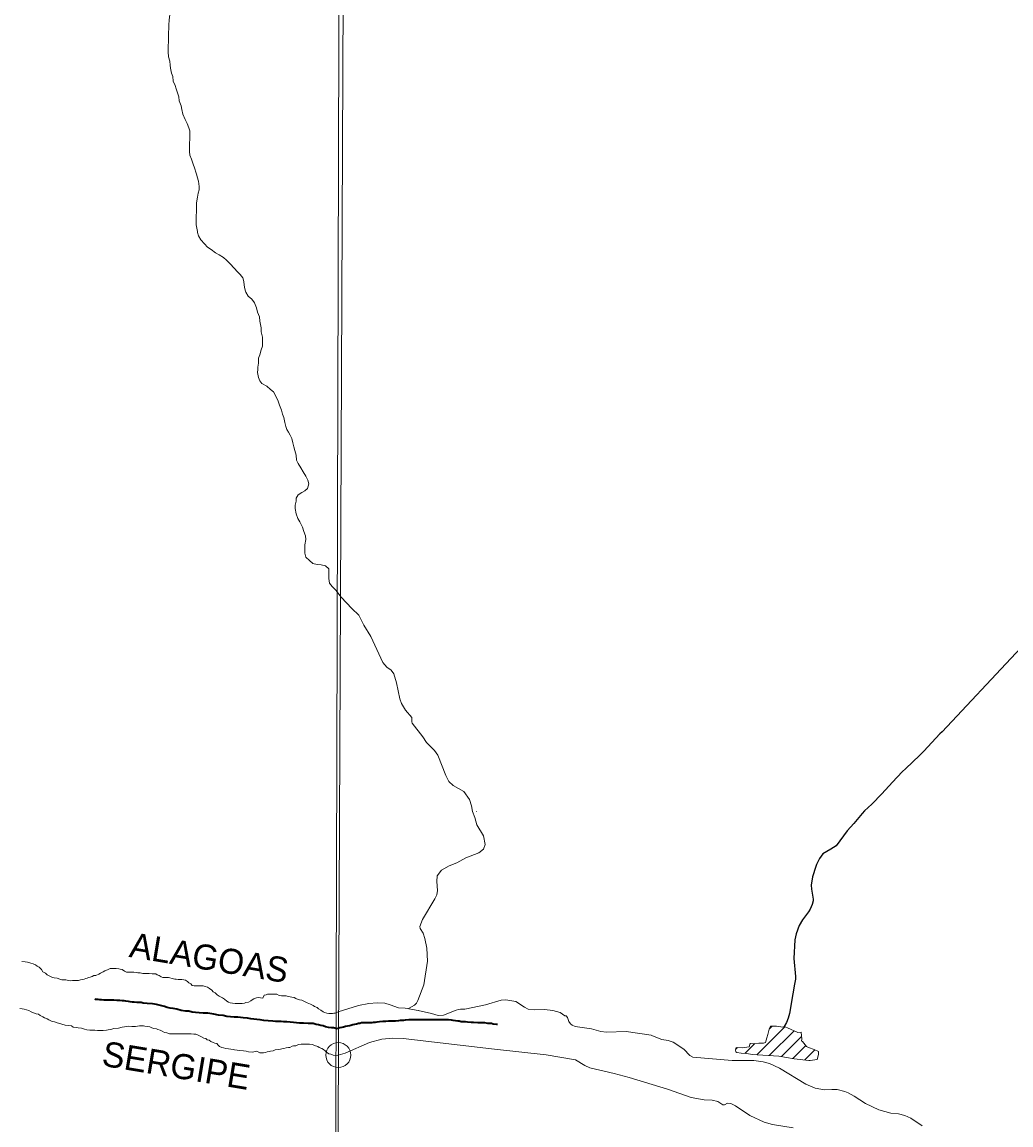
# Model space of a CAD drawing. Extents: x -1643653 to 4543381, y 1624270 to 13878484.
# Drawn here: x 595557 to 598718, y 8904168 to 8907693 of the extents above; entities that cross this region are included whole.
import ezdxf
from ezdxf.enums import TextEntityAlignment as Align

# ---------------------------------------------------------------- set-up
doc = ezdxf.new("R2010")
doc.units = 0
doc.header["$LTSCALE"] = 160
doc.header["$PDMODE"] = 32
doc.header["$PDSIZE"] = 80
doc.linetypes.add('LONG_DASH_SHORT_DASH', pattern=[9.9, 6, -1.2, 1.5, -1.2])
doc.layers.add('6', color=7, linetype='Continuous', lineweight=13)
doc.layers.add('60', color=7, linetype='Continuous', lineweight=13)

msp = doc.modelspace()

# ---------------------------------------------------------------- linework, layer by layer
at = {"layer": '6'}
for p, q in [((597009.3, 8905170.6), (597009.5, 8905170.5)), ((597905.6, 8904392.3), (597995.3, 8904482)), ((597945.7, 8904390), (598025, 8904469.3)), ((597946.4, 8904475.5), (597954.7, 8904483.9)), ((597984.9, 8904386.8), (598049.1, 8904451)), ((597838.3, 8904409.9), (597844.2, 8904415.7)), ((597867.6, 8904396.8), (597899.4, 8904428.5)), ((598021.1, 8904380.5), (598062.5, 8904421.9)), ((598059, 8904376), (598091.6, 8904408.6))]:
    msp.add_line(p, q, dxfattribs=at)
for points in [[(596655.5, 8924715.8), (596593.3, 8909930.3), (596531.7, 8896026.7)], [(596049.9, 8907479.9), (596046.2, 8907490.3), (596040.2, 8907503.9), (596038.8, 8907519.4), (596035.3, 8907529.4), (596031.9, 8907545.5), (596030.4, 8907555.5), (596029.5, 8907568.5), (596025.6, 8907582), (596024.6, 8907598.1), (596024.9, 8907649.1), (596025.4, 8907658.6), (596026, 8907674.1), (596026.5, 8907683.6), (596027.6, 8907700.1), (596029.2, 8907716.6), (596029.4, 8907756.2), (596027.9, 8907771.7), (596025, 8907786.7), (596022.6, 8907799.7), (596019.1, 8907808.8), (596014.2, 8907819.3), (596014.3, 8907828.6)], [(596115.7, 8907204.3), (596113.9, 8907210.7), (596108, 8907227.8), (596104.5, 8907239.3), (596099.1, 8907254.8), (596093.7, 8907267.4), (596092.7, 8907279.4), (596093, 8907346), (596090.6, 8907355.5), (596085.1, 8907369.5), (596078.2, 8907382.1), (596070.8, 8907398.6), (596067.8, 8907413.7), (596065.4, 8907425.2), (596059.4, 8907441.7), (596058, 8907454.7), (596055, 8907464.3), (596049.9, 8907479.9)], [(596117.5, 8907024.2), (596116.1, 8907034), (596114.2, 8907044.6), (596114.5, 8907115.1), (596118.1, 8907133.1), (596120.6, 8907146.6), (596123.2, 8907157.1), (596123.2, 8907168.1), (596121.3, 8907184.2), (596117.4, 8907198.2), (596115.7, 8907204.3)], [(596271.3, 8906832.7), (596268.8, 8906840.6), (596267.4, 8906852.6), (596266, 8906863.6), (596262.5, 8906875.6), (596254.5, 8906886.2), (596246.1, 8906895.2), (596235.1, 8906906.3), (596222.2, 8906920.4), (596211.2, 8906932.4), (596201.2, 8906941), (596187.3, 8906949.1), (596175.3, 8906955.7), (596161.8, 8906966.2), (596149.8, 8906973.8), (596139.9, 8906984.4), (596128.4, 8906996.9), (596121.5, 8907010), (596118, 8907020.5), (596117.5, 8907024.2)], [(596279.7, 8906817), (596272.3, 8906829.5), (596271.3, 8906832.7)], [(596461.2, 8906005.4), (596461.2, 8906022.7), (596463.8, 8906039.2), (596463.4, 8906051.2), (596457.4, 8906065.3), (596453.5, 8906078.3), (596444.6, 8906095.4), (596439.1, 8906106.9), (596433.7, 8906120.9), (596429.8, 8906138.5), (596429.8, 8906149), (596432.9, 8906162), (596433.9, 8906171.5), (596439.5, 8906182), (596451, 8906189.9), (596461, 8906195.4), (596470.1, 8906202.3), (596474.2, 8906216.8), (596471.2, 8906229.4), (596464.2, 8906241.4), (596455.8, 8906256), (596447.9, 8906268), (596439.9, 8906282.6), (596434.5, 8906292.6), (596433, 8906308.7), (596429.1, 8906323.7), (596426.2, 8906335.2), (596422.7, 8906348.8), (596419.3, 8906361.8), (596413.8, 8906373.3), (596408.8, 8906382.4), (596403.4, 8906390.9), (596399.9, 8906400.4), (596397, 8906413.4), (596393.6, 8906429), (596389.6, 8906440), (596386.2, 8906452.6), (596379.7, 8906468.6), (596376.3, 8906481.6), (596368.8, 8906497.2), (596361.4, 8906511.2), (596351.4, 8906519.3), (596340, 8906529.4), (596324, 8906537.5), (596317.3, 8906546.3), (596312.9, 8906557.6), (596309.7, 8906572.8), (596311, 8906582.9), (596310.7, 8906590.6), (596312.8, 8906603.1), (596313.4, 8906618.6), (596316.9, 8906629.1), (596321.5, 8906645.1), (596325.6, 8906657.6), (596326.1, 8906673.6), (596325.7, 8906686.1), (596321.8, 8906703.6), (596321.3, 8906715.7), (596317.4, 8906737.2), (596316.5, 8906750.7), (596310, 8906765.8), (596307.1, 8906779.8), (596300.2, 8906796.3), (596291.2, 8906807.9), (596279.7, 8906817)], [(596838.8, 8905408.9), (596804, 8905452.2), (596802.6, 8905456.8), (596803.3, 8905469.9), (596782.8, 8905493.9), (596770.6, 8905515.5), (596764.7, 8905530.2), (596754.3, 8905581.4), (596745.9, 8905609.6), (596737.4, 8905621.2), (596722.8, 8905631.7), (596710.6, 8905646), (596672.1, 8905729.1), (596650.2, 8905765.8), (596633.6, 8905797.4), (596611.2, 8905818.6), (596577.4, 8905855.5), (596559.7, 8905877.5), (596548.7, 8905888.6), (596540.2, 8905900.2), (596538.3, 8905914.2), (596537.9, 8905930.7), (596537.5, 8905945.2), (596527, 8905955.3), (596513.5, 8905957.9), (596500.5, 8905959.4), (596487, 8905962.5), (596476, 8905972.6), (596464.6, 8905983.1), (596461.1, 8905995.7), (596461.2, 8906005.4)], [(596792.7, 8904540.1), (596811.4, 8904551.1), (596818.4, 8904557.4), (596822.7, 8904565.5), (596841.5, 8904615.9), (596853.2, 8904691.8), (596850.7, 8904732.7), (596845.1, 8904764.5), (596839.3, 8904781), (596829.4, 8904796.5), (596828.9, 8904802.2), (596837.1, 8904824.7), (596877.1, 8904890.7), (596882.8, 8904903.4), (596885.5, 8904918), (596882.5, 8904946.3), (596884.2, 8904964.5), (596897.9, 8904982), (596922.6, 8904996.6), (596946.5, 8905006.2), (596975.3, 8905021.5), (597017.5, 8905037.8), (597031.8, 8905049.4), (597037, 8905065), (597032.3, 8905091.9), (597011.4, 8905127.4), (597004.9, 8905150.7), (596996.7, 8905170.4), (596994.1, 8905188.6), (596987.3, 8905208), (596969.8, 8905234), (596935.4, 8905253.2), (596921.5, 8905266.1), (596912.2, 8905285.1), (596886, 8905350.5), (596875.4, 8905364.7), (596850.4, 8905390), (596838.8, 8905408.9)], [(595556.5, 8904690.4), (595567.5, 8904689.9), (595575, 8904688.3), (595585.5, 8904685.2), (595593, 8904682.7), (595599.9, 8904679.7), (595605.9, 8904675.6), (595612.4, 8904672.1), (595619.8, 8904665.5), (595623.3, 8904658), (595631.8, 8904653.4), (595637.2, 8904647.4), (595645.7, 8904643.3), (595654.7, 8904639.7), (595659.7, 8904638.2), (595669.6, 8904637.1), (595677.6, 8904633.6), (595684.1, 8904631.5)], [(595684.1, 8904631.5), (595696.6, 8904631.9), (595710.6, 8904628.3), (595718.1, 8904629.3), (595722.1, 8904629.3), (595726.6, 8904629.7), (595733.1, 8904629.7), (595737.1, 8904630.2), (595744.1, 8904632.1), (595751.7, 8904633.1), (595756.2, 8904634.6), (595760.7, 8904636), (595765.2, 8904637), (595769.2, 8904639), (595774.7, 8904640.4), (595781.2, 8904642.4), (595786.8, 8904645.4), (595793.3, 8904646.3), (595802.8, 8904650.3), (595807.8, 8904653.7), (595816.9, 8904657.2), (595821.4, 8904660.7), (595830.4, 8904663.6), (595839, 8904668.1), (595845, 8904668), (595850, 8904668), (595858, 8904667.9), (595866, 8904667.4), (595870.5, 8904665.8), (595877.5, 8904664.8), (595884.9, 8904659.7), (595891.4, 8904656.2), (595899.4, 8904656.1), (595903.4, 8904656.1), (595910.9, 8904656.1), (595914.9, 8904656), (595922.9, 8904655), (595927.4, 8904654.4), (595934.9, 8904653.9), (595943.4, 8904652.3), (595951.4, 8904652.3), (595956.4, 8904652.3), (595963.4, 8904652.2), (595973.4, 8904651.6), (595980.4, 8904651.1), (595984.9, 8904650.6), (595989.4, 8904647.5), (595995.3, 8904646), (596002.3, 8904641.9), (596006.8, 8904639.9), (596012.8, 8904639.9), (596025.8, 8904639.8), (596041.3, 8904635.2), (596045.8, 8904634.6), (596050.3, 8904633.6), (596056.3, 8904633.1), (596063.8, 8904633), (596067.8, 8904633), (596074.3, 8904632.4), (596079.3, 8904630.4), (596086.2, 8904626.9), (596090.2, 8904622.3), (596097.2, 8904619.3), (596100.7, 8904614.2), (596107.2, 8904613.2), (596113.7, 8904613.2), (596120.7, 8904613.1), (596124.7, 8904613.1), (596128.7, 8904613.1), (596136.2, 8904613), (596142.2, 8904611), (596149.6, 8904608.4), (596156.1, 8904604.4), (596163.6, 8904599.3), (596168, 8904593.3), (596174.5, 8904590.2), (596180.5, 8904583.7), (596186.9, 8904580.1), (596193.4, 8904576.1), (596197.9, 8904574.1), (596204.4, 8904570), (596211.3, 8904563.4), (596217.3, 8904560.4), (596222.8, 8904558.9), (596229.8, 8904557.3), (596238.8, 8904556.3), (596245.3, 8904556.2), (596249.3, 8904556.2), (596255.8, 8904556.1), (596260.3, 8904556.6), (596268.3, 8904557.6), (596272.8, 8904559), (596280.8, 8904561), (596288.9, 8904564.4), (596292.9, 8904567.9), (596298.4, 8904570.9), (596307, 8904574.3), (596312, 8904575.3), (596327, 8904573.2), (596331.5, 8904582.7), (596337.5, 8904584.1)], [(596337.5, 8904584.1), (596341.6, 8904585.6), (596350.1, 8904586.6), (596357.6, 8904586.5), (596364.6, 8904586), (596371.1, 8904585.9), (596379.5, 8904581.9), (596386.5, 8904581.3), (596393.5, 8904581.3), (596401.5, 8904580.7), (596408, 8904579.2), (596414, 8904578.1), (596419, 8904576.6), (596427, 8904575.5), (596432, 8904572.5), (596440, 8904569.4), (596444.5, 8904567.9), (596452, 8904566.9), (596457.4, 8904563.3), (596468.4, 8904558.2), (596478.9, 8904554.7), (596487.3, 8904550.1), (596492.3, 8904546.6), (596500.3, 8904543), (596504.3, 8904539), (596511.7, 8904535.4), (596519.2, 8904529.4), (596523.7, 8904527.8), (596531.7, 8904525.8), (596538.2, 8904524.7), (596545.2, 8904524.7), (596549.2, 8904524.7), (596554.2, 8904525.1), (596558.2, 8904525.1), (596568.1, 8904529.4), (596633, 8904549.7), (596665.5, 8904556.5), (596692.3, 8904558.4), (596717.2, 8904557), (596733.8, 8904552.4)], [(596113, 8904457.9), (596106, 8904458.5), (596097.5, 8904459.1), (596092.5, 8904459.1), (596084.5, 8904459.1), (596079.5, 8904459.2), (596067.5, 8904459.2), (596057, 8904459.3), (596050, 8904459.4), (596042, 8904459.4), (596036.5, 8904459.5), (596028, 8904459.5), (596020, 8904462.6), (596012, 8904463.6), (596005, 8904467.7), (595998.5, 8904470.7), (595991.5, 8904472.8), (595987.1, 8904475.8), (595977.6, 8904476.9), (595969.6, 8904479.9), (595965.1, 8904481.5), (595958.6, 8904482.5), (595950.1, 8904484.1), (595945.1, 8904485.1), (595936.6, 8904485.2), (595932.1, 8904485.2), (595920.1, 8904482.3), (595908.6, 8904483.3), (595897.6, 8904483.4), (595892.1, 8904482.9), (595885.1, 8904482), (595877, 8904480.5), (595865, 8904477.1), (595851, 8904476.2), (595840.5, 8904473.3), (595832.5, 8904471.8), (595827, 8904470.9), (595816.4, 8904470.4), (595808.4, 8904470.5), (595798.4, 8904470.5), (595789.4, 8904470.6), (595783.9, 8904470.6), (595773.9, 8904470.7), (595763.9, 8904472.3), (595756.9, 8904473.8), (595747, 8904477.4), (595737, 8904478), (595730.5, 8904479.5), (595721, 8904481.1), (595715.5, 8904484.6), (595704.5, 8904485.7), (595695, 8904487.2), (595684.5, 8904490.3), (595678, 8904491.9), (595669.1, 8904494.9), (595661.1, 8904498), (595653.6, 8904499), (595649.1, 8904500.6), (595642.6, 8904503.6), (595637.6, 8904507.2), (595628.7, 8904510.2), (595623.7, 8904513.3), (595615.2, 8904518.3), (595609.7, 8904521.9), (595601.8, 8904522.9), (595593.3, 8904527), (595585.8, 8904529.5), (595579.3, 8904533.6), (595571.3, 8904536.1), (595563.8, 8904537.7), (595557.3, 8904539.7), (595550.4, 8904540.8)], [(596733.8, 8904552.4), (596760.4, 8904542.1), (596781.9, 8904541.7), (596822.9, 8904534.3)], [(596822.7, 8904565.5), (596818.4, 8904557.4), (596811.4, 8904551.1), (596792.7, 8904540.1)], [(596823.3, 8904534.6), (596822.9, 8904534.3), (596866.1, 8904524.6), (596887.5, 8904518.1), (596904.4, 8904518.5), (596944.7, 8904535.2), (596952.2, 8904537.4), (596959.2, 8904537.7), (596972.2, 8904538.7), (597038.5, 8904552.3), (597088.9, 8904566.9), (597103.5, 8904567.8), (597135.1, 8904562.2), (597163.3, 8904544.4), (597175.5, 8904538.6), (597195.2, 8904535.8), (597227.3, 8904537.4), (597253.9, 8904534.1), (597277.1, 8904527.3), (597291.9, 8904517.4), (597296.9, 8904516.7), (597300.6, 8904511.3), (597305.1, 8904499.1), (597310, 8904491.8), (597315.9, 8904486.6), (597325.4, 8904483.2), (597377.2, 8904474.8), (597406.8, 8904466.6), (597425.4, 8904464.6), (597488, 8904467), (597567.9, 8904454.9)], [(596137.9, 8904445.3), (596128.4, 8904450.8), (596120.5, 8904454.9), (596113, 8904457.9)], [(596412.8, 8904415.9), (596408.8, 8904415.9), (596401.3, 8904414.5), (596394.3, 8904413), (596387.2, 8904411.6), (596383.2, 8904410.6), (596376.2, 8904409.6), (596366.7, 8904408.2), (596360.2, 8904405.2), (596351.2, 8904404.3), (596347.2, 8904402.8), (596341.2, 8904401.9), (596335.1, 8904399.9), (596328.6, 8904398.9), (596324.1, 8904398.5), (596317.1, 8904398.5), (596307.2, 8904403.6), (596293.1, 8904401.2), (596281.1, 8904402.3), (596273.1, 8904403.8), (596264.6, 8904405.4), (596253.7, 8904406.4), (596244.7, 8904407.5), (596236.7, 8904408.1), (596232.2, 8904409.1), (596224.2, 8904410.2), (596216.7, 8904411.2), (596208.7, 8904412.8), (596201.2, 8904414.3), (596196.2, 8904415.8), (596188.7, 8904418.9), (596184.2, 8904422.9), (596179.3, 8904428), (596173.3, 8904429), (596167.8, 8904432.1), (596160.3, 8904435.1), (596155.8, 8904438.6), (596148.8, 8904439.7), (596144.9, 8904444.7), (596137.9, 8904445.3)], [(597784.5, 8904240.9), (597780.8, 8904243.5), (597763, 8904246.9), (597737.7, 8904248), (597696.4, 8904255.7), (597619.9, 8904282.1), (597498.2, 8904319.6), (597450, 8904332.9), (597372.6, 8904350.3), (597356, 8904357.7), (597326.5, 8904376.3), (597232.9, 8904391.8), (597058.1, 8904411.6), (596775.1, 8904444.1), (596742.4, 8904446), (596707.5, 8904442.8), (596667.4, 8904431.6), (596590.1, 8904397.6), (596568.1, 8904391.5), (596558.7, 8904389.9), (596551.2, 8904391.5), (596544.2, 8904394), (596537.7, 8904395.6), (596530.7, 8904401.1), (596526.2, 8904404.6), (596520.3, 8904409.2), (596515.8, 8904412.2), (596506.8, 8904415.8), (596502.3, 8904419.3), (596492.4, 8904422.4), (596485.4, 8904425.4), (596475.9, 8904426), (596467.4, 8904426.1), (596458.4, 8904426.1), (596449.4, 8904426.2), (596440.4, 8904425.2), (596431.8, 8904421.3), (596424.8, 8904421.3), (596420.3, 8904419.9), (596412.8, 8904415.9)], [(597567.9, 8904454.9), (597572.2, 8904452.6), (597602.6, 8904441.6), (597622.9, 8904438.2), (597638, 8904432.9), (597672.2, 8904410.2), (597691.4, 8904390.6), (597701.7, 8904384.3), (597826.9, 8904374.3), (597896.6, 8904373.8), (597926.2, 8904370), (597946.7, 8904364.9), (597978.4, 8904349.8), (598062.8, 8904298.6), (598092.1, 8904285.4), (598121.7, 8904280.6), (598145.7, 8904281.8), (598162.6, 8904280.9), (598187.1, 8904274.8), (598198.3, 8904270.4), (598217.2, 8904259.9), (598252.8, 8904236.5), (598295.7, 8904216.1), (598334.6, 8904205.9), (598358.9, 8904203.3), (598378.5, 8904198.1), (598398.6, 8904189.3), (598434, 8904165.6)], [(598021.9, 8904158.5), (597956.3, 8904169.2), (597929.3, 8904177.5), (597883.8, 8904198.6), (597837.6, 8904229.6), (597822.4, 8904236.9), (597812.2, 8904237.9), (597802.9, 8904232.5), (597797.6, 8904231.9), (597784.5, 8904240.9)]]:
    msp.add_lwpolyline(points, dxfattribs=at)
for points in [[(596575.8, 8909932.4), (585614.8, 8909969.8), (585583.8, 8898914.4), (596544.8, 8898874.9)], [(598076.1, 8904374.3), (598098.6, 8904377.3), (598102.8, 8904393.2), (598103.1, 8904402.4), (598089.5, 8904409.8), (598071, 8904415.8), (598065, 8904418.6), (598052.1, 8904435.2), (598049.2, 8904436.8), (598050, 8904442.7), (598047.6, 8904465), (598036.8, 8904463.8), (598004.4, 8904478.8), (597993.7, 8904482.5), (597989.2, 8904480.8), (597968.7, 8904483.6), (597949.6, 8904484), (597945.8, 8904474), (597941.6, 8904457.1), (597937.6, 8904447), (597933.3, 8904431.5), (597927.5, 8904429.7), (597912, 8904430), (597894.4, 8904427.9), (597885.2, 8904428.9), (597883.8, 8904426.4), (597882.9, 8904420.8), (597881.3, 8904418.1), (597859.9, 8904414.8), (597840.3, 8904416), (597837.6, 8904407.7), (597838.4, 8904401.7), (597841.9, 8904400), (597856, 8904397.5), (597873.8, 8904396.3), (597891.4, 8904393.1), (597976.5, 8904388.3), (598025.4, 8904379.8), (598072.1, 8904374.5)]]:
    msp.add_lwpolyline(points, close=True, dxfattribs=at)
at = {"layer": '6', "lineweight": 25}
for points in [[(598811.5, 8905757.4), (598733.5, 8905676.3), (598498.6, 8905424.2), (598490.9, 8905418), (598439.8, 8905363.3), (598425.4, 8905349.3)], [(598425.4, 8905349.3), (598382.1, 8905307.4), (598370, 8905296.7), (598339.1, 8905264), (598305.9, 8905226), (598273.9, 8905193.3), (598249.7, 8905171.9), (598243, 8905164.1)], [(598243, 8905164.1), (598215.7, 8905131.8), (598194.5, 8905108.4), (598159.2, 8905060.4), (598142.4, 8905049.3), (598117.3, 8905035), (598111.1, 8905027.6), (598105.9, 8905019.5), (598097.1, 8905000.6)], [(598097.1, 8905000.6), (598094.2, 8904994.3), (598084, 8904960.9), (598079.1, 8904934.7), (598081, 8904921.7)], [(598081, 8904921.7), (598085.6, 8904889.7), (598085.6, 8904884.2), (598082.7, 8904873.1), (598076, 8904857.5), (598071.3, 8904849.5), (598052.2, 8904824.1), (598041.5, 8904805.9), (598031.7, 8904779.5), (598027.3, 8904760), (598024.5, 8904700), (598029.9, 8904642.3), (598029.5, 8904633.9), (598026.3, 8904618.1), (598021.2, 8904587.6)], [(598021.2, 8904587.6), (598010.6, 8904524.8), (598006.1, 8904509.6), (598000.4, 8904495.6), (597993.4, 8904482.7)]]:
    msp.add_lwpolyline(points, dxfattribs=at)
at = {"layer": '6', "linetype": 'LONG_DASH_SHORT_DASH', "lineweight": 35}
for points in [[(596403.1, 8904497.6), (596393.1, 8904498.1), (596385.2, 8904498.7), (596380.2, 8904498.7), (596375.2, 8904499.2), (596367.2, 8904499.3), (596358.7, 8904499.8), (596344.2, 8904500.9), (596330.2, 8904502), (596318.2, 8904504.5), (596307.2, 8904505.1), (596298.2, 8904506.1), (596288.7, 8904507.2), (596278.2, 8904509.8), (596264.2, 8904510.3), (596247.2, 8904512.9), (596234.7, 8904513), (596223.2, 8904513.5), (596212.2, 8904514.6), (596200.3, 8904518.2), (596185.3, 8904519.2), (596169.8, 8904521.8), (596151.3, 8904524.9), (596136.3, 8904525), (596122.8, 8904526.1), (596111.8, 8904527.1), (596101.3, 8904528.2), (596090.4, 8904531.3), (596079.4, 8904531.8), (596065.9, 8904534.4), (596051.9, 8904538), (596040.4, 8904540.5), (596030.9, 8904541.1), (596021.4, 8904543.6), (596012, 8904546.7), (596000, 8904549.8), (595987, 8904552.8), (595974.5, 8904555.4), (595957.5, 8904556), (595944.5, 8904557.1), (595937.6, 8904559.6), (595929.5, 8904559.6), (595924, 8904559.7), (595915.6, 8904560.2), (595909.6, 8904560.7), (595903.1, 8904561.8), (595897.1, 8904562.3), (595889.1, 8904563.9), (595883.1, 8904564.4), (595877.1, 8904564.9), (595870.1, 8904566), (595860.6, 8904566), (595850.1, 8904566.6), (595840.6, 8904567.1), (595830.1, 8904567.2), (595819.1, 8904567.2), (595811.1, 8904567.8), (595805.6, 8904567.8), (595800.1, 8904568.8), (595791.6, 8904569.4), (595790.2, 8904569.7)], [(597057.4, 8904492), (597045.7, 8904492.5), (597036, 8904494), (597030.4, 8904494), (597021.8, 8904494.5), (597014.2, 8904494.5), (597000.4, 8904495.6), (596993.3, 8904496.1), (596981.1, 8904496.6), (596975, 8904497.6), (596965.8, 8904498.1), (596961.2, 8904498.1), (596954.1, 8904499.7), (596950, 8904500.2), (596942.9, 8904500.7), (596935.3, 8904501.7), (596929.7, 8904502.7), (596920, 8904503.7), (596907.3, 8904503.7), (596895.6, 8904503.7), (596890, 8904503.7), (596880.3, 8904503.7), (596874.2, 8904503.7), (596857.9, 8904503.7), (596850.8, 8904503.7), (596839.1, 8904503.7), (596833, 8904503.7), (596821.8, 8904503.7), (596815.7, 8904503.7), (596801.4, 8904503.7), (596793.8, 8904503.7), (596782.1, 8904502.7), (596776, 8904502.2), (596765.8, 8904501.7), (596760.7, 8904500.7), (596750.6, 8904499.6), (596741.9, 8904499.6), (596737.3, 8904499.6), (596728.7, 8904499.6), (596720.5, 8904498.6), (596710.8, 8904498.6), (596699.7, 8904498.1), (596691, 8904496.6), (596686.4, 8904496.1), (596679.3, 8904495.6), (596675.2, 8904494.5), (596665.6, 8904494), (596659.5, 8904494), (596654.4, 8904494), (596648.8, 8904494), (596642.7, 8904494), (596637.1, 8904492.5), (596633, 8904492.5), (596625.9, 8904490.4), (596620.3, 8904489.4), (596614.7, 8904487.9), (596608.6, 8904486.3), (596603.5, 8904484.8), (596597.4, 8904483.8), (596591.3, 8904482.3), (596585.2, 8904480.7), (596579.1, 8904479.7), (596573, 8904478.7), (596573, 8904478.7), (596573, 8904478.7)], [(596573, 8904478.7), (596564, 8904475.2), (596553, 8904478.3), (596546, 8904478.8), (596537, 8904479.3), (596527, 8904481.9), (596519.6, 8904484.9), (596512.1, 8904486), (596504.6, 8904488.5), (596497.1, 8904489.6), (596487.6, 8904492.1), (596479.1, 8904492.2), (596471.6, 8904492.7), (596456.6, 8904493.3), (596443.6, 8904493.9), (596434.1, 8904494.9), (596425.1, 8904495.5), (596414.6, 8904496.5), (596403.1, 8904497.6)], [(597076.6, 8904488.8), (597073.7, 8904489.4), (597063, 8904490.4), (597057.4, 8904492)]]:
    msp.add_lwpolyline(points, dxfattribs=at)
at = {"layer": '6'}
msp.add_point((596568.1, 8904391.5), dxfattribs=at)
at = {"layer": '60', "lineweight": 25}
msp.add_spline([(814781, 9009175.5), (814787.2, 9009173.4), (814796.9, 9009173.4), (814799.4, 9009172.4), (814805.1, 9009174.5), (814805.6, 9009176.5), (814811.7, 9009179.5), (814811.7, 9009179.5), (814801.5, 9009181), (814790.7, 9009181.5), (814784.1, 9009183.1), (814777.4, 9009185.1), (814778.4, 9009175.5)], degree=3, dxfattribs=at)

# ---------------------------------------------------------------- texts
at = {"layer": '6'}
for s, p in [('ALAGOAS', (596148.9, 8904663.4)), ('SERGIPE', (596043.6, 8904319))]:
    msp.add_text(s, height=80, rotation=350.533, dxfattribs=at).set_placement(p, align=Align.CENTER)

doc.saveas('drawing.dxf')
